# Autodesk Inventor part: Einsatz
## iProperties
Created: 2007-01
Part Number: Einsatz
Document SubType Name: Modeling
Designer: Kumpf
Manufacturer: Standard
Standards Organization: Custom
Author: Kumpf
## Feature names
1. Drehung1 [Revolution]
2. Fase1 [Chamfer]
